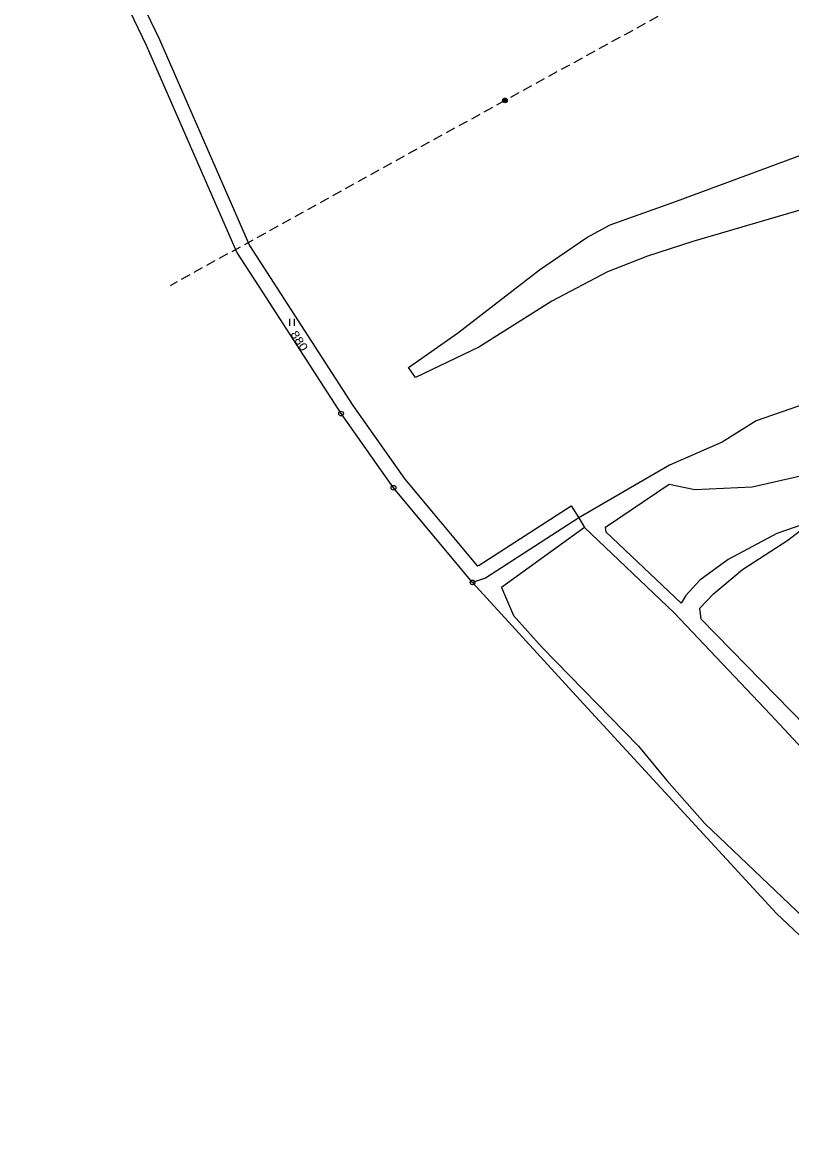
# Model space of a CAD drawing. Extents: x -754445 to -751443, y -1030748 to -1028224.
# Drawn here: x -754443.4 to -754280.2, y -1028801.1 to -1028563 of the extents above; entities that cross this region are included whole.
import ezdxf
from ezdxf.enums import TextEntityAlignment as Align

# ---------------------------------------------------------------- set-up
doc = ezdxf.new("R2010")
doc.units = 0
doc.header["$LTSCALE"] = 0.68
doc.linetypes.add('MEDIUM_DASHED', pattern=[4.5, 3, -1.5])
for name, color, linetype, lineweight in [('1', 7, 'Continuous', 25), ('3', 7, 'Continuous', 25), ('6', 7, 'Continuous', 25), ('8', 7, 'Continuous', 25)]:
    doc.layers.add(name, color=color, linetype=linetype, lineweight=lineweight)
doc.layers.add('2', color=7, linetype='Continuous')

msp = doc.modelspace()

# ---------------------------------------------------------------- linework, layer by layer
at = {"layer": '1'}
for p, q in [((-754375.81, -1028646.06), (-754393.22, -1028619.1)), ((-754364.68, -1028661.82), (-754375.81, -1028646.06)), ((-754231.95, -1028801.06), (-754283.35, -1028752.23))]:
    msp.add_line(p, q, dxfattribs=at)
for points in [[(-754417.11, -1028567.89), (-754440.66, -1028518.83), (-754443.45, -1028508.59)], [(-754430.14, -1028511.99), (-754436.5, -1028513.24), (-754437.84, -1028517.78), (-754414.38, -1028566.64), (-754395.28, -1028610.38), (-754373.32, -1028644.38), (-754362.3, -1028659.99), (-754346.92, -1028678.42), (-754346.48, -1028678.27), (-754326.97, -1028665.65), (-754325.34, -1028668.17)], [(-754393.22, -1028619.1), (-754397.93, -1028611.8), (-754417.11, -1028567.89)], [(-754276.26, -1028602.21), (-754301.14, -1028609.5), (-754310.79, -1028612.64), (-754319.25, -1028615.95), (-754331.09, -1028622.21), (-754346.6, -1028631.93), (-754360.04, -1028638.39), (-754361.53, -1028636.31), (-754351.13, -1028629.02), (-754333.67, -1028615.52), (-754323.64, -1028608.66), (-754318.69, -1028605.99), (-754304.59, -1028600.98), (-754277.62, -1028590.98)], [(-754270.12, -1028641.52), (-754287.67, -1028647.61), (-754294.9, -1028652.13), (-754306.12, -1028657.02), (-754325.34, -1028668.17), (-754324.12, -1028670.25)], [(-754273.95, -1028715.68), (-754299.38, -1028689.71), (-754299.67, -1028687.36), (-754296.75, -1028684.33), (-754290.6, -1028679.14), (-754280.97, -1028672.91), (-754275.75, -1028668.89), (-754283.29, -1028671.56), (-754293.67, -1028677.04), (-754299.67, -1028681.45), (-754302.63, -1028684.69), (-754303.63, -1028686.33), (-754319.54, -1028671.24), (-754319.67, -1028670.2), (-754306.14, -1028661.06), (-754300.7, -1028662.21), (-754288.58, -1028661.59), (-754277.64, -1028659.11)], [(-754283.35, -1028752.23), (-754325.93, -1028705.99), (-754347.91, -1028681.92), (-754364.68, -1028661.82)], [(-754325.34, -1028668.17), (-754345.16, -1028680.99), (-754347.91, -1028681.92)], [(-754324.12, -1028670.25), (-754341.75, -1028682.99), (-754339.18, -1028688.92), (-754333.09, -1028695.73), (-754312.68, -1028716.71), (-754306.68, -1028723.96), (-754298.56, -1028733.1), (-754262.66, -1028767.36)], [(-754324.12, -1028670.25), (-754305.07, -1028688.4), (-754284.66, -1028709.94), (-754255.8, -1028740.96), (-754251.74, -1028744.08), (-754248.54, -1028746.01), (-754242.17, -1028749.48), (-754233.82, -1028757.78), (-754230.36, -1028763.63), (-754226.82, -1028771.21)]]:
    msp.add_lwpolyline(points, dxfattribs=at)
at = {"layer": '3'}
for p, q in [((-754386.721, -1028627.42), (-754386.721, -1028625.92)), ((-754385.72, -1028627.42), (-754385.72, -1028625.92))]:
    msp.add_line(p, q, dxfattribs=at)
at = {"layer": '6', "linetype": 'MEDIUM_DASHED'}
msp.add_lwpolyline([(-754129.99, -1028463.21), (-754199.91, -1028501.36), (-754270.98, -1028541.17), (-754341.02, -1028579.57), (-754412.06, -1028618.91)], dxfattribs=at)
at = {"layer": '6'}
for radius in [0.5, 0.4, 0.3, 0.2, 0.1]:
    msp.add_circle((-754341.0234, -1028579.5699), radius, dxfattribs=at)
at = {"layer": '8'}
for centre, radius in [((-754375.81, -1028646.0599), 0.5), ((-754375.81, -1028646.0599), 0.0303), ((-754364.68, -1028661.8199), 0.5), ((-754364.68, -1028661.8199), 0.0303), ((-754347.91, -1028681.9199), 0.5), ((-754347.91, -1028681.9199), 0.0303)]:
    msp.add_circle(centre, radius, dxfattribs=at)

# ---------------------------------------------------------------- texts
at = {"layer": '2', "width": 1.2}
msp.add_text('880', height=1.7, rotation=303, dxfattribs=at).set_placement((-754385.3769, -1028631.0801), align=Align.CENTER)

doc.saveas('drawing.dxf')
